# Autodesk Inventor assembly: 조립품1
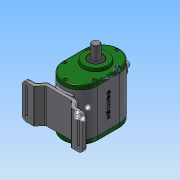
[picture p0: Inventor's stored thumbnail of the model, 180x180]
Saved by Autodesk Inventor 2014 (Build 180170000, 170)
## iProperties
Created: 2018-07
Part Number: 조립품1
Document SubType Name: Assembly
Designer: 학생용
Mass: 1458.16 g
Surface Area: 2005.93 cm^2
Volume: 678.331 cm^3
Density: 2.14963 g/cm^3
Author: 학생용
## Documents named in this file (14)
- C:\Users\학생용\Desktop\380707V1001\조립품1.iam
- C:\Users\학생용\Desktop\380707V1001\본체.ipt
- C:\Users\학생용\Desktop\380707V1001\메인축.ipt
- C:\Users\학생용\Desktop\380707V1001\서브축.ipt
- C:\Users\학생용\Desktop\380707V1001\베어링 608.ipt
- C:\Users\학생용\Desktop\380707V1001\베어링 6003.ipt
- C:\Users\학생용\Desktop\380707V1001\앞커버.ipt
- C:\Users\학생용\Desktop\380707V1001\오일 실 17 32 8.ipt
- C:\Users\학생용\Desktop\380707V1001\볼트 M4.ipt
- C:\Users\학생용\Desktop\380707V1001\뒤커버.ipt
- C:\Users\학생용\Desktop\380707V1001\오일 실 8 22 7.ipt
- C:\Users\학생용\Desktop\380707V1001\슬라이더.ipt
- C:\Users\학생용\Desktop\380707V1001\가변스프링.ipt
- C:\Users\학생용\Desktop\380707V1001\부시.ipt
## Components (1 placed, 1 different names)
1. 가변스프링:1
